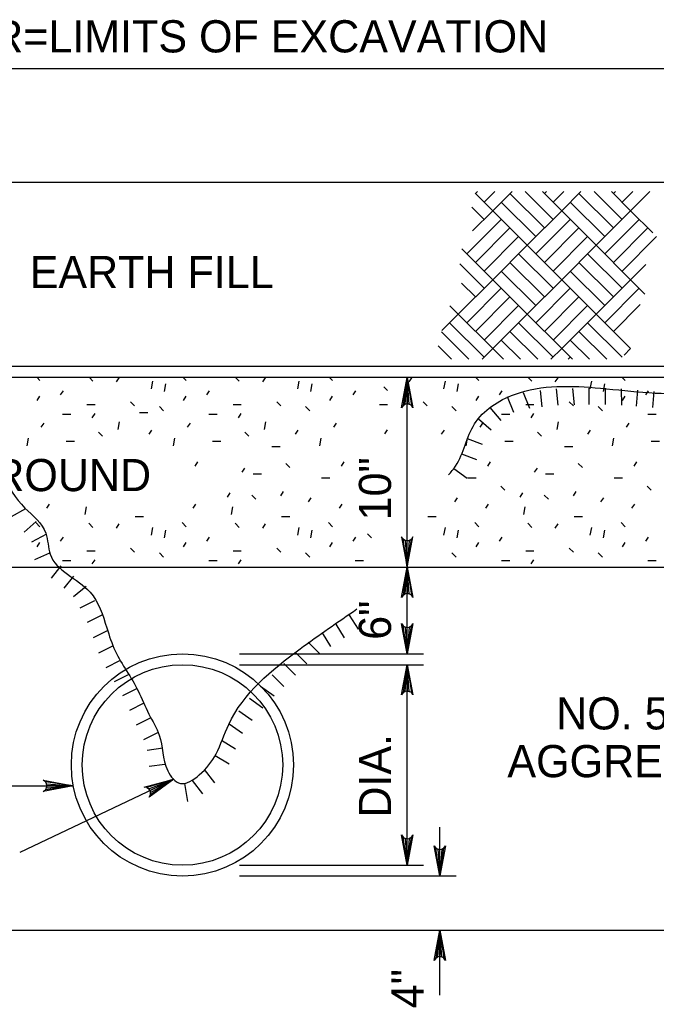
# Model space of a CAD drawing. Extents: x 1.32 to 7.47, y -3.56 to 5.14.
# Drawn here: x 3.503 to 4.69, y 3.303 to 5.144 of the extents above; entities that cross this region are included whole.
import ezdxf

# ---------------------------------------------------------------- set-up
doc = ezdxf.new("R2010")
doc.units = 0
for name, color, linetype in [('DETL-DIMS', 7, 'Continuous'), ('DETL-LINE', 7, 'Continuous'), ('DETL-NOTE', 7, 'Continuous'), ('DETL-PATT', 7, 'Continuous')]:
    doc.layers.add(name, color=color, linetype=linetype)

msp = doc.modelspace()

# ---------------------------------------------------------------- linework, layer by layer
at = {"layer": 'DETL-DIMS'}
for p, q in [((5.0188, 5.0529), (2.5946, 5.0529)), ((4.2259, 4.1236), (4.2259, 4.4772)), ((4.2259, 3.962), (4.2259, 4.1236)), ((3.9128, 3.962), (4.2562, 3.962)), ((3.9128, 3.9418), (4.2562, 3.9418)), ((4.2259, 3.5681), (4.2259, 3.9418)), ((3.5043, 3.5926), (3.7909, 3.7283)), ((3.2445, 3.7159), (3.6033, 3.7159)), ((4.2865, 3.5479), (4.2865, 3.6388)), ((3.9128, 3.5681), (4.2562, 3.5681)), ((3.9128, 3.5479), (4.3168, 3.5479)), ((4.2865, 3.3257), (4.2865, 3.4469))]:
    msp.add_line(p, q, dxfattribs=at)
for points in [[(4.2259, 4.4772), (4.2365, 4.4207), (4.2335, 4.425), (4.2297, 4.4273), (4.2259, 4.4279), (4.2221, 4.4273), (4.2183, 4.425), (4.2153, 4.4207), (4.2259, 4.4772), (4.2183, 4.425), (4.2221, 4.4273), (4.2259, 4.4772), (4.2259, 4.4279), (4.2297, 4.4273), (4.2259, 4.4772), (4.2335, 4.425)], [(4.2259, 4.1236), (4.2365, 4.1801), (4.2335, 4.1758), (4.2297, 4.1735), (4.2259, 4.1729), (4.2221, 4.1735), (4.2183, 4.1758), (4.2153, 4.1801), (4.2259, 4.1236), (4.2183, 4.1758), (4.2221, 4.1735), (4.2259, 4.1236), (4.2259, 4.1729), (4.2297, 4.1735), (4.2259, 4.1236), (4.2335, 4.1758)], [(4.2259, 4.1236), (4.2365, 4.0671), (4.2335, 4.0715), (4.2297, 4.0737), (4.2259, 4.0744), (4.2221, 4.0737), (4.2183, 4.0715), (4.2153, 4.0671), (4.2259, 4.1236), (4.2183, 4.0715), (4.2221, 4.0737), (4.2259, 4.1236), (4.2259, 4.0744), (4.2297, 4.0737), (4.2259, 4.1236), (4.2335, 4.0715)], [(4.2259, 3.962), (4.2153, 4.0185), (4.2183, 4.0142), (4.2221, 4.0119), (4.2259, 4.0113), (4.2297, 4.0119), (4.2335, 4.0142), (4.2365, 4.0185), (4.2259, 3.962), (4.2335, 4.0142), (4.2297, 4.0119), (4.2259, 3.962), (4.2259, 4.0113), (4.2221, 4.0119), (4.2259, 3.962), (4.2183, 4.0142)], [(4.2259, 3.9418), (4.2365, 3.8853), (4.2335, 3.8897), (4.2297, 3.8919), (4.2259, 3.8926), (4.2221, 3.8919), (4.2183, 3.8897), (4.2153, 3.8853), (4.2259, 3.9418), (4.2183, 3.8897), (4.2221, 3.8919), (4.2259, 3.9418), (4.2259, 3.8926), (4.2297, 3.8919), (4.2259, 3.9418), (4.2335, 3.8897)], [(3.6033, 3.7159), (3.5468, 3.7053), (3.5512, 3.7083), (3.5534, 3.7121), (3.5541, 3.7159), (3.5534, 3.7197), (3.5512, 3.7235), (3.5468, 3.7265), (3.6033, 3.7159), (3.5512, 3.7235), (3.5534, 3.7197), (3.6033, 3.7159), (3.5541, 3.7159), (3.5534, 3.7121), (3.6033, 3.7159), (3.5512, 3.7083)], [(3.7909, 3.7283), (3.7444, 3.6946), (3.747, 3.6992), (3.7474, 3.7036), (3.7464, 3.7073), (3.7442, 3.7104), (3.7406, 3.7129), (3.7353, 3.7137), (3.7909, 3.7283), (3.7406, 3.7129), (3.7442, 3.7104), (3.7909, 3.7283), (3.7464, 3.7073), (3.7474, 3.7036), (3.7909, 3.7283), (3.747, 3.6992)], [(4.2259, 3.5681), (4.2153, 3.6246), (4.2183, 3.6202), (4.2221, 3.618), (4.2259, 3.6173), (4.2297, 3.618), (4.2335, 3.6202), (4.2365, 3.6246), (4.2259, 3.5681), (4.2335, 3.6202), (4.2297, 3.618), (4.2259, 3.5681), (4.2259, 3.6173), (4.2221, 3.618), (4.2259, 3.5681), (4.2183, 3.6202)], [(4.2865, 3.5479), (4.2759, 3.6044), (4.2789, 3.6), (4.2827, 3.5978), (4.2865, 3.5971), (4.2903, 3.5978), (4.2941, 3.6), (4.2971, 3.6044), (4.2865, 3.5479), (4.2941, 3.6), (4.2903, 3.5978), (4.2865, 3.5479), (4.2865, 3.5971), (4.2827, 3.5978), (4.2865, 3.5479), (4.2789, 3.6)], [(4.2865, 3.4469), (4.2971, 3.3904), (4.2941, 3.3947), (4.2903, 3.397), (4.2865, 3.3976), (4.2827, 3.397), (4.2789, 3.3947), (4.2759, 3.3904), (4.2865, 3.4469), (4.2789, 3.3947), (4.2827, 3.397), (4.2865, 3.4469), (4.2865, 3.3976), (4.2903, 3.397), (4.2865, 3.4469), (4.2941, 3.3947)]]:
    msp.add_lwpolyline(points, dxfattribs=at)
at = {"layer": 'DETL-LINE'}
for p, q in [((5.0188, 4.8408), (2.5946, 4.8408)), ((5.1877, 4.4974), (2.4245, 4.4974)), ((5.1837, 4.4772), (2.4245, 4.4772)), ((2.5946, 4.1236), (5.0188, 4.1236)), ((2.5946, 3.4469), (5.0188, 3.4469))]:
    msp.add_line(p, q, dxfattribs=at)
for radius in [0.2071, 0.1869]:
    msp.add_circle((3.8067, 3.7549), radius, dxfattribs=at)
for points in [[(2.5946, 4.5663), (2.6396, 4.5513), (2.8471, 4.5356), (2.9725, 4.5474), (3.0782, 4.5395), (3.137, 4.5278), (3.2975, 4.5239), (3.3093, 4.5239), (3.3602, 4.5239), (3.3824, 4.4974), (3.4581, 4.3828), (3.4738, 4.2966), (3.513, 4.2339), (3.5521, 4.1868), (3.56, 4.1477), (3.6344, 4.0771), (3.6657, 4.0105), (3.6814, 3.9674), (3.7244, 3.8929), (3.744, 3.8498), (3.7636, 3.8106), (3.7793, 3.744), (3.8028, 3.7205), (3.838, 3.7362), (3.8694, 3.7754), (3.8929, 3.8302), (4.026, 3.9713), (4.132, 4.0457)], [(4.3029, 4.2955), (4.3159, 4.3122), (4.3511, 4.3906), (4.4255, 4.4455), (4.5861, 4.4572), (4.7663, 4.4494), (4.9386, 4.5121), (5.0182, 4.5814)]]:
    msp.add_spline(points, degree=3, dxfattribs=at)
at = {"layer": 'DETL-PATT'}
for p, q in [((4.353, 4.8202), (4.3568, 4.824)), ((4.3691, 4.8042), (4.389, 4.824)), ((4.3852, 4.7881), (4.4211, 4.824)), ((4.4977, 4.772), (4.4456, 4.824)), ((4.5137, 4.7881), (4.4778, 4.824)), ((4.4816, 4.8202), (4.4854, 4.824)), ((4.4977, 4.8042), (4.5175, 4.824)), ((4.5137, 4.7881), (4.5497, 4.824)), ((4.6262, 4.772), (4.5742, 4.824)), ((4.6423, 4.7881), (4.6063, 4.824)), ((4.6102, 4.8202), (4.614, 4.824)), ((4.6262, 4.8042), (4.6461, 4.824)), ((4.6423, 4.7881), (4.6783, 4.824)), ((4.3852, 4.7881), (4.3527, 4.8206)), ((4.4816, 4.7559), (4.4173, 4.8202)), ((4.6102, 4.7559), (4.5459, 4.8202)), ((4.3691, 4.772), (4.3464, 4.7947)), ((4.3476, 4.7505), (4.3852, 4.7881)), ((4.4494, 4.7238), (4.3852, 4.7881)), ((4.4655, 4.7399), (4.4012, 4.8042)), ((4.4494, 4.7238), (4.5137, 4.7881)), ((4.578, 4.7238), (4.5137, 4.7881)), ((4.5941, 4.7399), (4.5298, 4.8042)), ((4.578, 4.7238), (4.6423, 4.7881)), ((4.6837, 4.7467), (4.6423, 4.7881)), ((4.337, 4.7077), (4.4012, 4.772)), ((4.4655, 4.7077), (4.5298, 4.772)), ((4.5941, 4.7077), (4.6584, 4.772)), ((4.353, 4.6917), (4.4173, 4.7559)), ((4.4816, 4.6917), (4.5459, 4.7559)), ((4.6102, 4.6917), (4.6744, 4.7559)), ((4.3691, 4.6756), (4.4334, 4.7399)), ((4.4977, 4.6756), (4.5619, 4.7399)), ((4.6262, 4.6756), (4.6905, 4.7399)), ((4.3852, 4.6595), (4.3275, 4.7172)), ((4.3852, 4.6595), (4.4494, 4.7238)), ((4.5137, 4.6595), (4.4494, 4.7238)), ((4.5137, 4.6595), (4.578, 4.7238)), ((4.6423, 4.6595), (4.578, 4.7238)), ((4.4977, 4.6435), (4.4334, 4.7077)), ((4.6262, 4.6435), (4.5619, 4.7077)), ((4.3691, 4.6435), (4.3237, 4.6889)), ((4.4816, 4.6274), (4.4173, 4.6917)), ((4.6102, 4.6274), (4.5459, 4.6917)), ((4.6423, 4.6595), (4.6707, 4.6879)), ((4.3209, 4.5952), (4.3852, 4.6595)), ((4.4494, 4.5952), (4.3852, 4.6595)), ((4.4655, 4.6113), (4.4012, 4.6756)), ((4.4494, 4.5952), (4.5137, 4.6595)), ((4.578, 4.5952), (4.5137, 4.6595)), ((4.5941, 4.6113), (4.5298, 4.6756)), ((4.578, 4.5952), (4.6423, 4.6595)), ((4.669, 4.6328), (4.6423, 4.6595)), ((4.353, 4.6274), (4.3272, 4.6532)), ((4.337, 4.5792), (4.4012, 4.6435)), ((4.4655, 4.5792), (4.5298, 4.6435)), ((4.5941, 4.5792), (4.6584, 4.6435)), ((4.353, 4.5631), (4.4173, 4.6274)), ((4.4816, 4.5631), (4.5459, 4.6274)), ((4.3209, 4.5952), (4.3055, 4.6107)), ((4.3691, 4.547), (4.4334, 4.6113)), ((4.4977, 4.547), (4.5619, 4.6113)), ((4.6102, 4.5631), (4.6602, 4.6131)), ((4.2904, 4.5648), (4.3209, 4.5952)), ((4.3852, 4.531), (4.3209, 4.5952)), ((4.3852, 4.531), (4.4494, 4.5952)), ((4.5137, 4.531), (4.4494, 4.5952)), ((4.5137, 4.531), (4.578, 4.5952)), ((4.6423, 4.531), (4.578, 4.5952)), ((4.3691, 4.5149), (4.3048, 4.5792)), ((4.4977, 4.5149), (4.4334, 4.5792)), ((4.6262, 4.5149), (4.5619, 4.5792)), ((4.3408, 4.5111), (4.2898, 4.5621)), ((4.4694, 4.5111), (4.4173, 4.5631)), ((4.5979, 4.5111), (4.5459, 4.5631)), ((4.3086, 4.5111), (4.2835, 4.5362)), ((4.3653, 4.5111), (4.3852, 4.531)), ((4.4051, 4.5111), (4.3852, 4.531)), ((4.4372, 4.5111), (4.4012, 4.547)), ((4.4938, 4.5111), (4.5137, 4.531)), ((4.5336, 4.5111), (4.5137, 4.531)), ((4.5658, 4.5111), (4.5298, 4.547)), ((4.63, 4.5187), (4.6423, 4.531)), ((4.526, 4.5111), (4.5298, 4.5149)), ((3.5356, 4.4772), (3.5411, 4.4717)), ((3.6332, 4.4772), (3.6399, 4.4704)), ((3.6836, 4.4691), (3.6887, 4.4768)), ((3.8083, 4.4772), (3.8138, 4.4717)), ((3.9059, 4.4772), (3.9127, 4.4704)), ((3.9563, 4.4691), (3.9615, 4.4768)), ((4.081, 4.4772), (4.0865, 4.4717)), ((4.2291, 4.4691), (4.2342, 4.4768)), ((4.3537, 4.4772), (4.3592, 4.4717)), ((4.4513, 4.4772), (4.4581, 4.4704)), ((4.5018, 4.4691), (4.5069, 4.4768)), ((4.6265, 4.4772), (4.632, 4.4717)), ((3.7508, 4.4704), (3.7483, 4.4563)), ((3.7752, 4.4652), (3.7727, 4.4511)), ((4.0236, 4.4704), (4.021, 4.4563)), ((4.048, 4.4652), (4.0454, 4.4511)), ((4.1821, 4.4596), (4.1888, 4.4528)), ((4.2963, 4.4704), (4.2937, 4.4563)), ((4.3207, 4.4652), (4.3181, 4.4511)), ((4.5035, 4.4561), (4.5067, 4.4255)), ((4.5339, 4.4566), (4.5371, 4.4263)), ((4.5643, 4.4571), (4.5646, 4.4267)), ((4.569, 4.4704), (4.5665, 4.4563)), ((4.5934, 4.4652), (4.5909, 4.4511)), ((4.5946, 4.4574), (4.5949, 4.427)), ((4.6249, 4.4561), (4.6252, 4.4257)), ((3.5359, 4.4344), (3.5411, 4.4421)), ((3.5796, 4.4447), (3.5847, 4.4524)), ((3.8086, 4.4344), (3.8138, 4.4421)), ((3.8523, 4.4447), (3.8574, 4.4524)), ((4.0814, 4.4344), (4.0865, 4.4421)), ((4.125, 4.4447), (4.1302, 4.4524)), ((4.3541, 4.4344), (4.3592, 4.4421)), ((4.3978, 4.4447), (4.4029, 4.4524)), ((4.4244, 4.4122), (4.4126, 4.4413)), ((4.4543, 4.4193), (4.4423, 4.4487)), ((4.4733, 4.453), (4.4766, 4.4224)), ((4.6268, 4.4344), (4.632, 4.4421)), ((4.6552, 4.4538), (4.6528, 4.4238)), ((4.6705, 4.4447), (4.6756, 4.4524)), ((4.6854, 4.4514), (4.683, 4.4213)), ((3.6284, 4.4267), (3.6438, 4.4267)), ((3.7097, 4.4319), (3.7175, 4.4242)), ((3.7637, 4.4229), (3.7714, 4.4152)), ((3.9011, 4.4267), (3.9165, 4.4267)), ((3.9825, 4.4319), (3.9902, 4.4242)), ((4.0364, 4.4229), (4.0441, 4.4152)), ((4.1738, 4.4267), (4.1892, 4.4267)), ((4.2552, 4.4319), (4.2629, 4.4242)), ((4.3091, 4.4229), (4.3168, 4.4152)), ((4.3796, 4.4214), (4.4003, 4.3973)), ((4.4466, 4.4267), (4.462, 4.4267)), ((4.5279, 4.4319), (4.5356, 4.4242)), ((4.5819, 4.4229), (4.5896, 4.4152)), ((3.5834, 4.4087), (3.5988, 4.4087)), ((3.6387, 4.4023), (3.6438, 4.41)), ((3.7269, 4.412), (3.7423, 4.412)), ((3.8562, 4.4087), (3.8716, 4.4087)), ((3.9114, 4.4023), (3.9165, 4.41)), ((4.4016, 4.4087), (4.417, 4.4087)), ((4.4568, 4.4023), (4.462, 4.41)), ((4.6743, 4.4087), (4.6897, 4.4087)), ((3.5436, 4.3843), (3.5488, 4.3921)), ((3.6887, 4.3946), (3.6862, 4.3805)), ((3.8163, 4.3843), (3.8215, 4.3921)), ((3.9615, 4.3946), (3.9589, 4.3805)), ((4.0891, 4.3843), (4.0942, 4.3921)), ((4.3823, 4.3793), (4.3584, 4.3996)), ((4.3618, 4.3843), (4.3669, 4.3921)), ((4.5069, 4.3946), (4.5044, 4.3805)), ((4.6345, 4.3843), (4.6397, 4.3921)), ((3.5192, 4.3638), (3.5166, 4.3497)), ((3.6502, 4.3753), (3.6579, 4.3676)), ((3.7444, 4.3715), (3.7496, 4.3792)), ((3.7919, 4.3638), (3.7894, 4.3497)), ((3.923, 4.3753), (3.9307, 4.3676)), ((4.0172, 4.3715), (4.0223, 4.3792)), ((4.0647, 4.3638), (4.0621, 4.3497)), ((4.1841, 4.372), (4.1892, 4.3797)), ((4.2899, 4.3715), (4.295, 4.3792)), ((4.3374, 4.3638), (4.3348, 4.3497)), ((4.3376, 4.3632), (4.3652, 4.353)), ((4.4684, 4.3753), (4.4761, 4.3676)), ((4.5626, 4.3715), (4.5677, 4.3792)), ((4.6101, 4.3638), (4.6076, 4.3497)), ((3.5898, 4.3587), (3.6053, 4.3587)), ((3.8626, 4.3587), (3.878, 4.3587)), ((3.9735, 4.3484), (3.9889, 4.3484)), ((4.408, 4.3587), (4.4234, 4.3587)), ((4.5189, 4.3484), (4.5343, 4.3484)), ((4.6808, 4.3587), (4.6962, 4.3587)), ((4.3271, 4.3348), (4.3547, 4.3246)), ((3.8305, 4.312), (3.8356, 4.3197)), ((3.9178, 4.3004), (3.9229, 4.3081)), ((3.9992, 4.3171), (4.0069, 4.3094)), ((4.1032, 4.312), (4.1083, 4.3197)), ((4.3127, 4.3078), (4.3373, 4.2896)), ((4.3759, 4.312), (4.3811, 4.3197)), ((4.4633, 4.3004), (4.4684, 4.3081)), ((4.5446, 4.3171), (4.5523, 4.3094)), ((4.6487, 4.312), (4.6538, 4.3197)), ((3.9383, 4.2978), (3.9538, 4.2978)), ((4.066, 4.2901), (4.0814, 4.2901)), ((4.3387, 4.2901), (4.3541, 4.2901)), ((4.4838, 4.2978), (4.4992, 4.2978)), ((4.6114, 4.2901), (4.6268, 4.2901)), ((4.4003, 4.2747), (4.408, 4.267)), ((4.6731, 4.2747), (4.6808, 4.267)), ((3.8908, 4.2542), (3.896, 4.2619)), ((3.9358, 4.258), (3.9435, 4.2503)), ((3.9902, 4.2567), (3.9953, 4.2645)), ((4.0416, 4.2452), (4.0467, 4.2529)), ((4.3143, 4.2452), (4.3194, 4.2529)), ((4.4363, 4.2542), (4.4414, 4.2619)), ((4.4812, 4.258), (4.4889, 4.2503)), ((4.5356, 4.2567), (4.5408, 4.2645)), ((4.587, 4.2452), (4.5921, 4.2529)), ((3.5539, 4.2336), (3.559, 4.2413)), ((3.6271, 4.2362), (3.6245, 4.2221)), ((3.8266, 4.2336), (3.8318, 4.2413)), ((3.8998, 4.2362), (3.8973, 4.2221)), ((4.0993, 4.2336), (4.1045, 4.2413)), ((4.3721, 4.2336), (4.3772, 4.2413)), ((4.4453, 4.2362), (4.4427, 4.2221)), ((4.6448, 4.2336), (4.6499, 4.2413)), ((3.514, 4.2325), (3.4874, 4.2175)), ((3.7187, 4.2182), (3.7342, 4.2182)), ((3.9915, 4.2182), (4.0069, 4.2182)), ((4.2642, 4.2182), (4.2796, 4.2182)), ((4.5369, 4.2182), (4.5523, 4.2182)), ((3.5339, 4.2089), (3.5116, 4.1887)), ((3.5333, 4.2066), (3.5411, 4.1989)), ((3.6322, 4.2054), (3.6399, 4.1977)), ((3.6836, 4.1964), (3.6887, 4.2041)), ((3.7508, 4.1977), (3.7483, 4.1835)), ((3.8061, 4.2066), (3.8138, 4.1989)), ((3.905, 4.2054), (3.9127, 4.1977)), ((3.9563, 4.1964), (3.9615, 4.2041)), ((4.0236, 4.1977), (4.021, 4.1835)), ((4.0788, 4.2066), (4.0865, 4.1989)), ((4.2963, 4.1977), (4.2937, 4.1835)), ((4.3515, 4.2066), (4.3592, 4.1989)), ((4.4504, 4.2054), (4.4581, 4.1977)), ((4.5018, 4.1964), (4.5069, 4.2041)), ((4.569, 4.1977), (4.5665, 4.1835)), ((4.6243, 4.2066), (4.632, 4.1989)), ((3.553, 4.1854), (3.5254, 4.17)), ((3.5796, 4.172), (3.5847, 4.1797)), ((3.7752, 4.1925), (3.7727, 4.1784)), ((3.8523, 4.172), (3.8574, 4.1797)), ((4.048, 4.1925), (4.0454, 4.1784)), ((4.125, 4.172), (4.1302, 4.1797)), ((4.1516, 4.1858), (4.1593, 4.1781)), ((4.3207, 4.1925), (4.3181, 4.1784)), ((4.3978, 4.172), (4.4029, 4.1797)), ((4.5934, 4.1925), (4.5909, 4.1784)), ((4.6705, 4.172), (4.6756, 4.1797)), ((3.5359, 4.1617), (3.5411, 4.1694)), ((3.8086, 4.1617), (3.8138, 4.1694)), ((4.0814, 4.1617), (4.0865, 4.1694)), ((4.3541, 4.1617), (4.3592, 4.1694)), ((4.6268, 4.1617), (4.632, 4.1694)), ((3.5588, 4.1498), (3.5309, 4.1373)), ((3.6284, 4.154), (3.6438, 4.154)), ((3.7097, 4.1591), (3.7175, 4.1514)), ((3.7637, 4.1501), (3.7714, 4.1424)), ((3.9011, 4.154), (3.9165, 4.154)), ((3.9825, 4.1591), (3.9902, 4.1514)), ((4.0364, 4.1501), (4.0441, 4.1424)), ((4.3091, 4.1501), (4.3168, 4.1424)), ((4.4466, 4.154), (4.462, 4.154)), ((4.5279, 4.1591), (4.5356, 4.1514)), ((4.5819, 4.1501), (4.5896, 4.1424)), ((3.5802, 4.1259), (3.562, 4.1033)), ((3.5834, 4.136), (3.5988, 4.136)), ((3.6387, 4.1296), (3.6438, 4.1373)), ((3.8562, 4.136), (3.8716, 4.136)), ((3.9114, 4.1296), (3.9165, 4.1373)), ((4.1289, 4.136), (4.1443, 4.136)), ((4.4016, 4.136), (4.417, 4.136)), ((4.4568, 4.1296), (4.462, 4.1373)), ((4.6743, 4.136), (4.6897, 4.136)), ((3.6038, 4.107), (3.5857, 4.0844)), ((3.6272, 4.0877), (3.6035, 4.0681)), ((3.6426, 4.0611), (3.6154, 4.0474)), ((3.6563, 4.0341), (3.629, 4.0203)), ((4.1177, 4.0342), (4.1341, 4.0081)), ((4.0927, 4.0172), (4.1085, 3.992)), ((3.6675, 4.0058), (3.6403, 3.992)), ((4.0669, 4.0012), (4.0828, 3.9759)), ((3.6774, 3.9769), (3.6502, 3.9631)), ((4.0414, 3.984), (4.0627, 3.9621)), ((4.0183, 3.9642), (4.0389, 3.9432)), ((3.6907, 3.9496), (3.6636, 3.9359)), ((3.9959, 3.9438), (4.0172, 3.922)), ((3.7068, 3.9238), (3.6797, 3.9101)), ((3.9742, 3.9227), (3.9955, 3.9009)), ((3.7221, 3.8976), (3.6951, 3.8839)), ((3.9777, 3.8831), (3.9525, 3.9009)), ((3.7349, 3.8701), (3.7078, 3.8564)), ((3.9567, 3.8608), (3.9316, 3.8786)), ((3.937, 3.8376), (3.9119, 3.8554)), ((3.7475, 3.8425), (3.7205, 3.8289)), ((3.9187, 3.8135), (3.894, 3.8309)), ((3.7612, 3.8155), (3.7342, 3.8018)), ((3.8798, 3.8008), (3.9059, 3.7849)), ((3.7701, 3.786), (3.7408, 3.7821)), ((3.7741, 3.756), (3.7448, 3.7521)), ((3.8677, 3.7726), (3.8938, 3.7568)), ((3.867, 3.7215), (3.8481, 3.7464)), ((3.8108, 3.7202), (3.8163, 3.6866)), ((3.8447, 3.7009), (3.8255, 3.726))]:
    msp.add_line(p, q, dxfattribs=at)

# ---------------------------------------------------------------- texts
at = {"layer": 'DETL-NOTE'}
for s, p in [('VARIABLE DIAMETER=LIMITS OF EXCAVATION', (2.6807, 5.0832)), ('EARTH FILL', (3.5219, 4.6438)), ('ORIGINAL GROUND', (2.986, 4.2653)), ('NO. 57', (4.5035, 3.8211)), ('AGGREGATE', (4.4125, 3.732))]:
    msp.add_text(s, height=0.06, dxfattribs=at).set_placement(p)
for s, p in [('10"', (4.1956, 4.2108)), ('6"', (4.1956, 3.9882)), ('DIA.', (4.1956, 3.6567)), ('4"', (4.2562, 3.3013))]:
    msp.add_text(s, height=0.06, rotation=90, dxfattribs=at).set_placement(p)

doc.saveas('drawing.dxf')
